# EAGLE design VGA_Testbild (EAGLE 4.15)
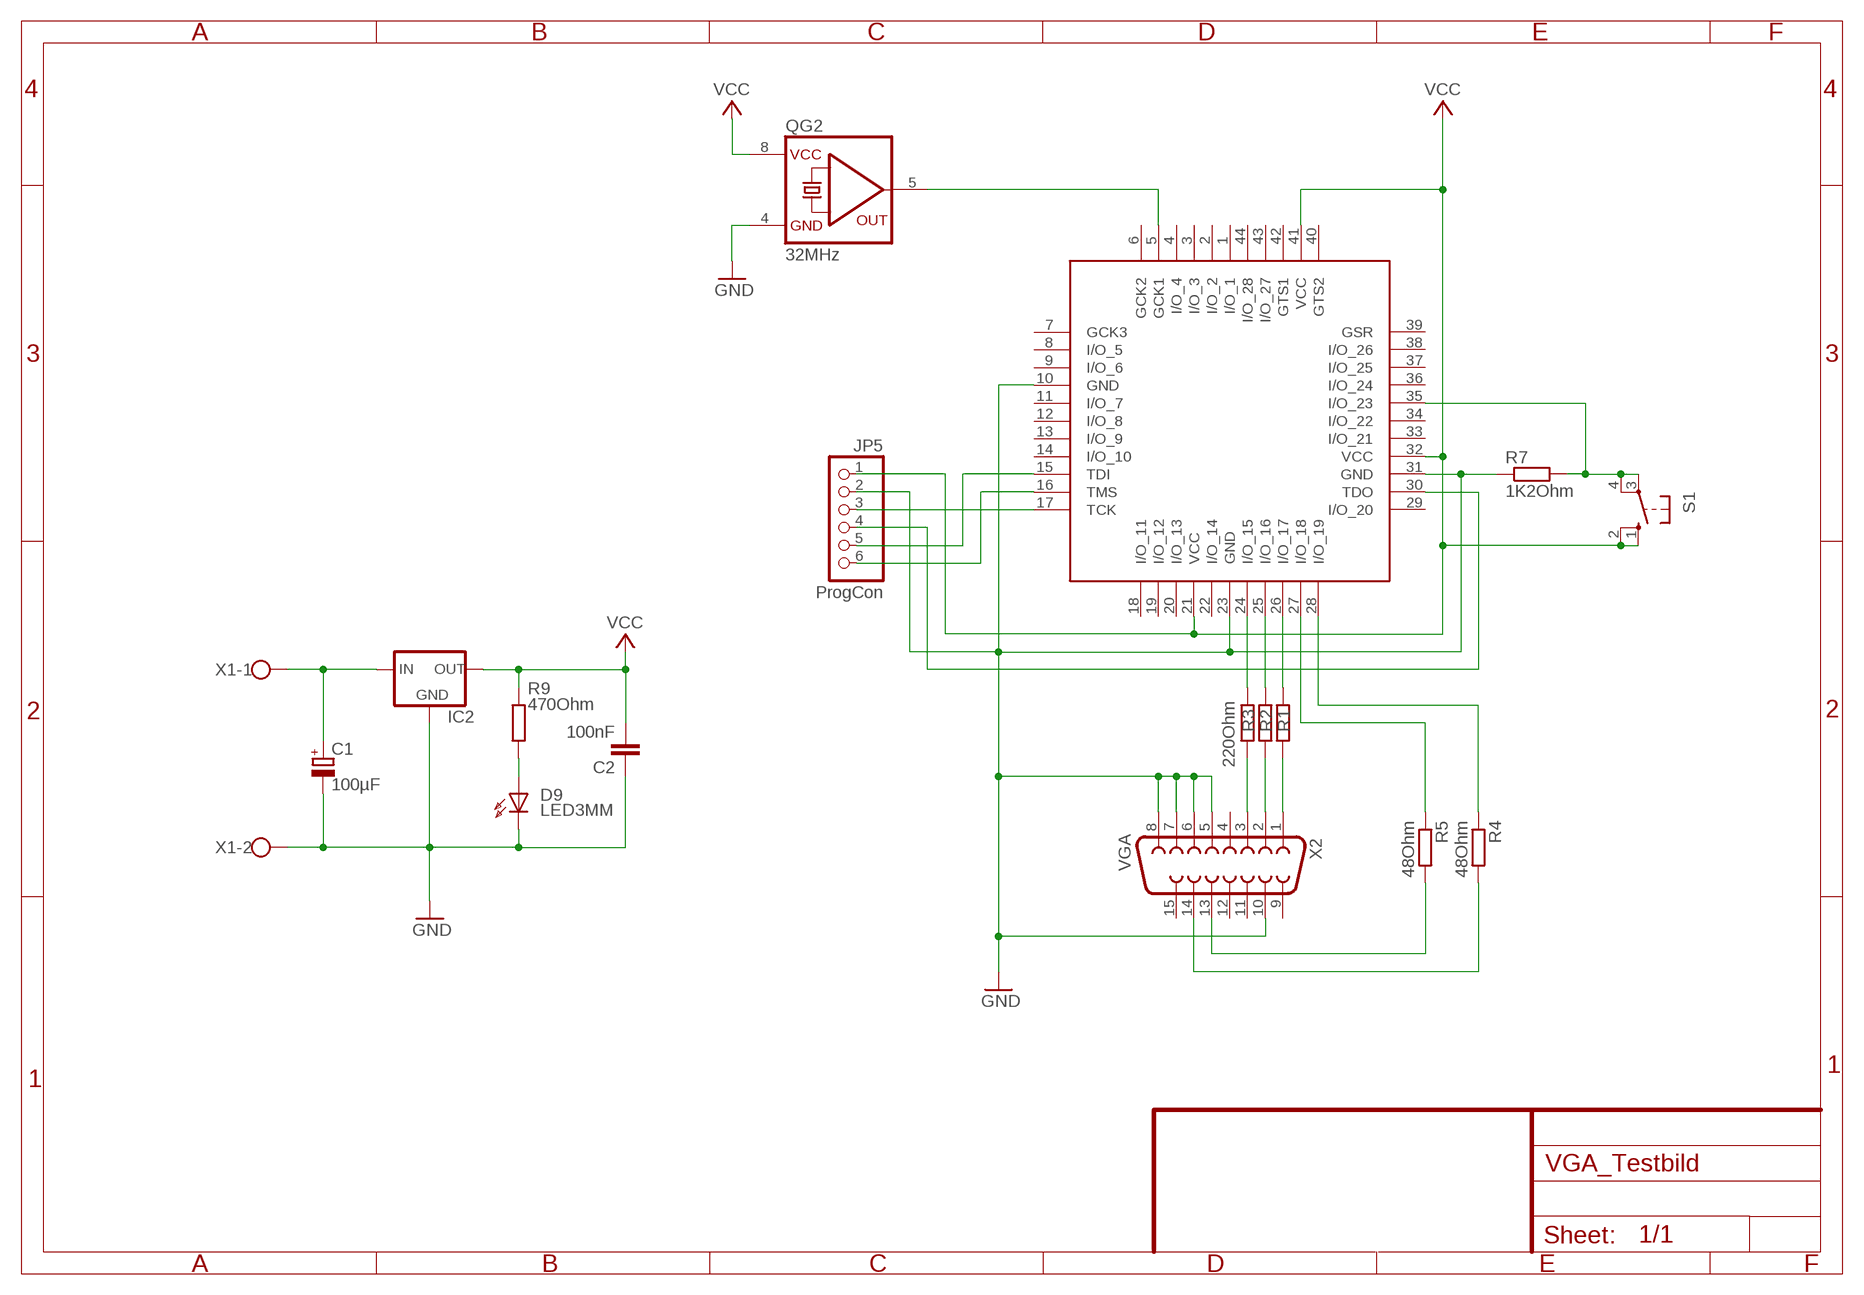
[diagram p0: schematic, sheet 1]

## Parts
C1  100µF  CPOL-EUE2.5-6  [E2,5-6]
C2  100nF  C-EU050-025X075  [C050-025X075]
D9  LED3MM  [LED3MM]
IC1  XC9536PLCC44S  [S44]
IC2  78XXL  [78XXL]
JP5  ProgCon  PINHD-1X6  [1X06]
QG2  32MHz  QG5460  [DIL08S]
R1  R-EU_0207/10  [0207/10]
R2  R-EU_0207/10  [0207/10]
R3  220Ohm  R-EU_0207/10  [0207/10]
R4  48Ohm  R-EU_0207/10  [0207/10]
R5  48Ohm  R-EU_0207/10  [0207/10]
R7  1K2Ohm  R-EU_0207/10  [0207/10]
R9  470Ohm  R-EU_0207/10  [0207/10]
S1  10-XX  [B3F-10XX]
X1  W237-02P  [W237-132]
X2  VGA  F15HDH  [HDF15H]

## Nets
GND: C1.- C2.1 D9.K(C) IC1.10(GND) IC1.23(GND) IC1.31(GND) IC2.GND JP5.2 QG2.4(GND) R7.1 X1.2 X2.5 X2.6 X2.7 X2.8 X2.10
N$1: R3.1 X2.3
N$2: R2.1 X2.2
N$3: R1.1 X2.1
N$4: IC1.24(I/O_15) R3.2
N$5: IC1.25(I/O_16) R2.2
N$6: IC1.26(I/O_17) R1.2
N$7: R5.2 X2.13
N$8: R4.2 X2.14
N$9: IC1.27(I/O_18) R5.1
N$10: IC1.15(TDI) JP5.5
N$11: IC1.16(TMS) JP5.6
N$12: IC1.17(TCK) JP5.3
N$13: IC1.28(I/O_19) R4.1
N$14: IC1.5(GCK1) QG2.5(OUT)
N$15: IC1.35(I/O_23) R7.2 S1.3(P) S1.4(P1)
N$22: IC1.30(TDO) JP5.4
N$47: C1.+ IC2.IN X1.1
N$48: D9.A R9.1
VCC: C2.2 IC1.21(VCC) IC1.32(VCC) IC1.41(VCC) IC2.OUT JP5.1 QG2.8(VCC) R9.2 S1.1(S) S1.2(S1)
Unconnected: IC1.1(I/O_1) IC1.2(I/O_2) IC1.3(I/O_3) IC1.4(I/O_4) IC1.6(GCK2) IC1.7(GCK3) IC1.8(I/O_5) IC1.9(I/O_6) IC1.11(I/O_7) IC1.12(I/O_8) IC1.13(I/O_9) IC1.14(I/O_10) IC1.18(I/O_11) IC1.19(I/O_12) IC1.20(I/O_13) IC1.22(I/O_14) IC1.29(I/O_20) IC1.33(I/O_21) IC1.34(I/O_22) IC1.36(I/O_24) IC1.37(I/O_25) IC1.38(I/O_26) IC1.39(GSR) IC1.40(GTS2) IC1.42(GTS1) IC1.43(I/O_27) IC1.44(I/O_28) X2.4 X2.9 X2.11 X2.12 X2.15

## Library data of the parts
C1 = rcl:CPOL-EU: POLARIZED CAPACITOR, European symbol
C2 = rcl:C-EU: CAPACITOR, European symbol
D9 = led:LED3MM: LED
IC1 = xilinx:XC9536: Xilinx CPLD Cells 36 Gates 800
IC2 = v-reg:78XXL: VOLTAGE REGULATOR
JP5 = pinhead:PINHD-1X6: PIN HEADER
QG2 = crystal:QG5460: CRYSTAL RESONATOR
R1-R5 R7 R9 = rcl:R-EU_: RESISTOR, European symbol
S1 = switch-omron:10-XX: OMRON SWITCH
X1 = con-wago-508:W237-02P: WAGO SREW CLAMP
X2 = con-subd:F15: SUB-D

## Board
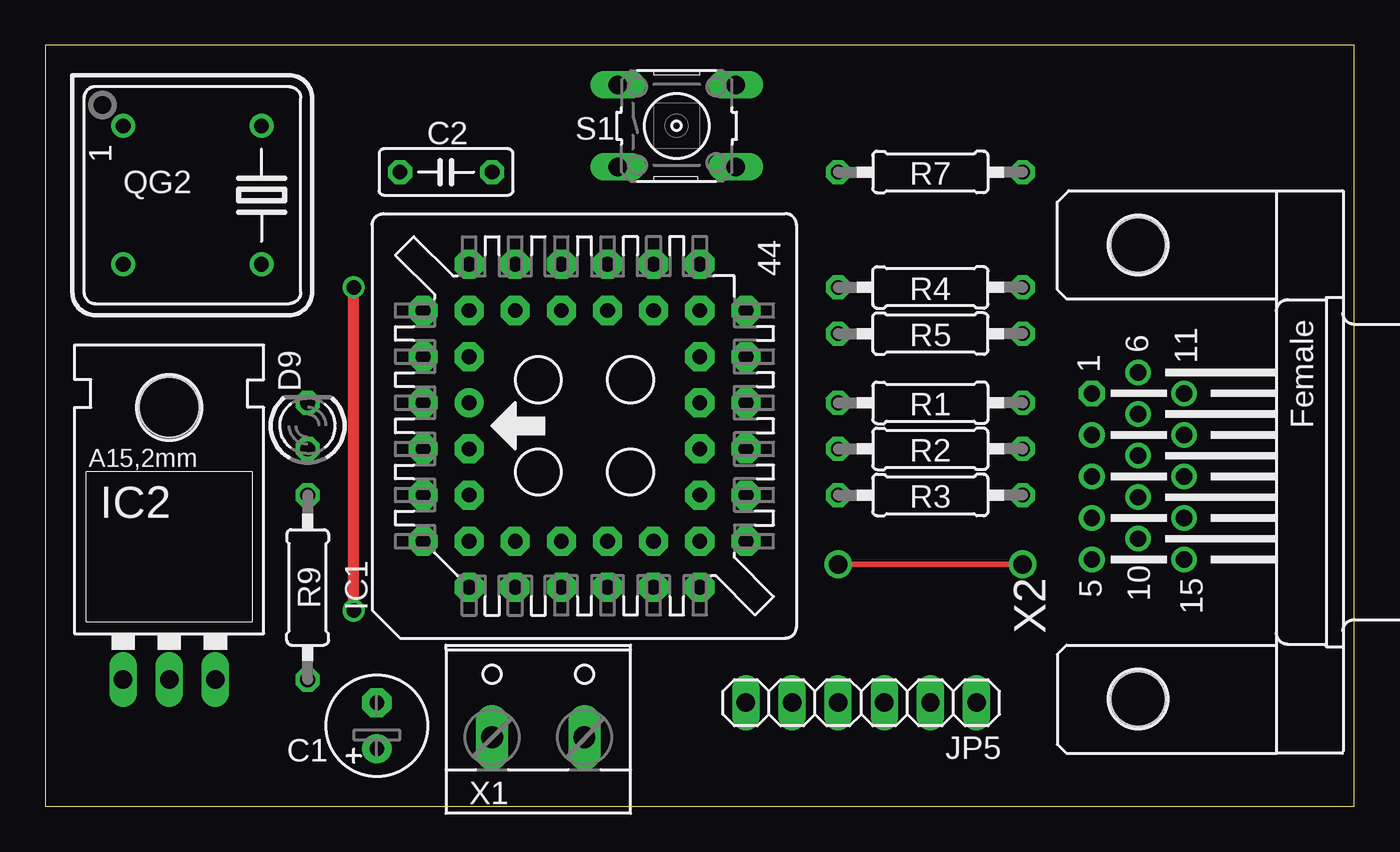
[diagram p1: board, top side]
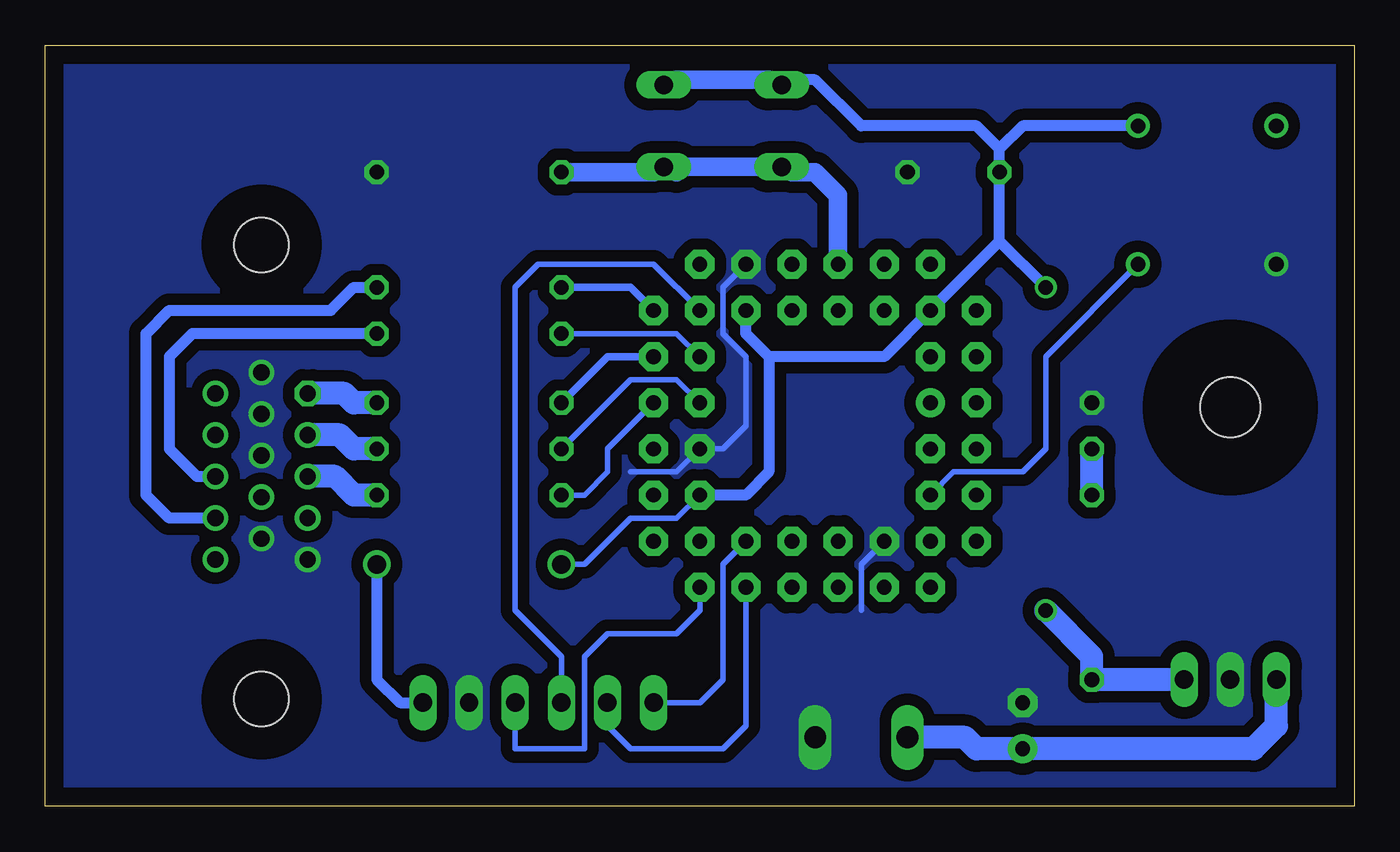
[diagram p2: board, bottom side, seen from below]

Size 72.06 x 41.89 mm. Coordinates in mm from the lower left corner, seen from the top.
Outline: 72.06,0 72.06,41.89 0,41.89 0,0 72.06,0
Copper layers (1*16): Top 0.035mm / dielectric 1.5mm / Bottom 0.035mm
Design rules "default": minimum track width 10mil, minimum drill 24mil, track to track 8mil, track to pad 8mil, pad to pad 8mil, via to via 8mil, smd to smd 8mil, copper to edge 40mil, drill to drill 8mil, minimum pad ring 10mil, minimum via ring 8mil, stop-mask expansion 4mil, vias tented up to drill 0mil, thermal gap 10mil

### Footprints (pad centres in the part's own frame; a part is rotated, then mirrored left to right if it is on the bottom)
E2,5-6 = drill 0.813 pad 1.6 round: + -1.27,0 | drill 0.813 pad 1.6 octagon: - 1.27,0
C050-025X075 = drill 0.813 octagon: 1 -2.54,0; 2 2.54,0
LED3MM = drill 0.813 octagon: A -1.27,0; K 1.27,0
S44 = drill 0.813 pad 1.6 round: 1 1.27,5.08 | drill 0.813 pad 1.6 octagon: 2 -1.27,7.62; 3 -1.27,5.08; 4 -3.81,7.62; 5 -3.81,5.08; 6 -6.35,7.62; 7 -8.89,5.08; 8 -6.35,5.08; 9 -8.89,2.54; 10 -6.35,2.54; 11 -8.89,0; 12 -6.35,0; 13 -8.89,-2.54; 14 -6.35,-2.54; 15 -8.89,-5.08; 16 -6.35,-5.08; 17 -8.89,-7.62; 18 -6.35,-10.16; 19 -6.35,-7.62; 20 -3.81,-10.16; 21 -3.81,-7.62; 22 -1.27,-10.16; 23 -1.27,-7.62; 24 1.27,-10.16; 25 1.27,-7.62; 26 3.81,-10.16; 27 3.81,-7.62; 28 6.35,-10.16; 29 8.89,-7.62; 30 6.35,-7.62; 31 8.89,-5.08; 32 6.35,-5.08; 33 8.89,-2.54; 34 6.35,-2.54; 35 8.89,0; 36 6.35,0; 37 8.89,2.54; 38 6.35,2.54; 39 8.89,5.08; 40 6.35,7.62; 41 6.35,5.08; 42 3.81,7.62; 43 3.81,5.08; 44 1.27,7.62
78XXL = drill 1.016 long: GND 0,-3.81; IN -2.54,-3.81; OUT 2.54,-3.81 | hole 3.302: 0,11.176
1X06 = drill 1.016 long: 1 -6.35,0; 2 -3.81,0; 3 -1.27,0; 4 1.27,0; 5 3.81,0; 6 6.35,0
DIL08S = drill 0.813 round: 1 -3.81,-3.81; 4 3.81,-3.81; 5 3.81,3.81; 8 -3.81,3.81
0207/10 = drill 0.813 octagon: 1 -5.08,0; 2 5.08,0
B3F-10XX = drill 1.016 long: 1 -3.251,2.261; 2 3.251,2.261; 3 -3.251,-2.261; 4 3.251,-2.261
W237-132 = drill 1.194 long: 1 -2.54,-0.635; 2 2.54,-0.635
HDF15H = drill 0.9 octagon: 1 4.329,2.54 | drill 0.9 round: 2 2.043,2.54; 3 -0.243,2.54; 4 -2.529,2.54; 5 -4.815,2.54; 6 5.472,0; 7 3.186,0; 8 0.9,0; 9 -1.386,0; 10 -3.672,0; 11 4.329,-2.54; 12 2.043,-2.54; 13 -0.243,-2.54; 14 -2.529,-2.54; 15 -4.815,-2.54 | hole 3: -12.5,0; 12.5,0

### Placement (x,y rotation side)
C1  18.25,4.44 90 top
C2  22.06,34.92 180 top
D9  14.44,20.95 90 top
IC1  28.41,20.95 90 top
IC2  6.82,10.79 0 top
JP5  44.92,5.71 180 top
QG2  8.09,33.65 270 top
R1  48.73,22.22 180 top
R2  48.73,19.68 180 top
R3  48.73,17.14 180 top
R4  48.73,28.57 0 top
R5  48.73,26.03 0 top
R7  48.73,34.92 180 top
R9  14.44,12.06 270 top
S1  34.76,37.46 0 top
X1  27.14,4.44 0 top
X2  60.16,18.41 90 top

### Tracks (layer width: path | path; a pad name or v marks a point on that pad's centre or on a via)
GND
  Bottom 0.305: IC1.10 27.14,13.33 27.14,10.79 | IC1.31 34.76,28.57 34.76,26.03 33.49,24.76 33.49,20.95 34.76,19.68 IC1.23 37.3,18.41 39.84,18.41
  pour Bottom (isolate 0.635, no thermals): 0.47,0.63 0.47,41.27 71.59,41.27 71.59,0.63
N$1
  Bottom 1.27: R3.1 55.08,17.14 56.11,18.17 X2.3
N$2
  Bottom 1.27: R2.1 55.08,19.68 55.85,20.45 X2.2
N$3
  Bottom 1.27: R1.1 55.08,22.22 55.6,22.74 X2.1
N$4
  Bottom 0.305: IC1.24 41.11,19.68 41.11,18.41 42.38,17.14 R3.2
N$5
  Bottom 0.305: IC1.25 37.3,23.49 39.84,23.49 R2.2
N$6
  Bottom 0.406: IC1.26 41.11,24.76 R1.2
N$7
  Bottom 0.61: X2.13 63.73,18.17 65.24,19.68 65.24,24.76 63.97,26.03 R5.2
N$8
  Bottom 0.61: R4.2 55.08,28.57 56.35,27.3 65.24,27.3 66.51,26.03 66.51,17.14 65.24,15.87 X2.14
N$9
  Bottom 0.305: IC1.27 37.3,26.03 R5.1
N$10
  Bottom 0.305: IC1.15 33.49,4.44 34.76,3.17 39.84,3.17 41.11,4.44 JP5.5
N$11
  Bottom 0.305: IC1.16 34.76,13.33 34.76,6.98 36.03,5.71 JP5.6
N$12
  Bottom 0.305: IC1.17 36.03,10.79 37.3,9.52 41.11,9.52 42.38,8.25 42.38,3.17 46.19,3.17 JP5.3
N$13
  Bottom 0.406: IC1.28 39.84,28.57 R4.1
N$14
  Bottom 0.305: IC1.5 22.06,18.41 18.25,18.41 16.98,19.68 16.98,24.76 QG2.5
N$15
  Bottom 0.406: 31.23,35.2 S1.3 | 37.02,35.2 37.3,34.92 | S1.4 38.29,35.2
  Bottom 1.016: IC1.35 28.41,33.65 29.68,34.92 30.95,34.92 31.23,35.2 | S1.3 37.02,35.2 | S1.4 37.58,35.2 37.3,34.92 | 38.29,35.2 38.57,34.92 R7.2
N$22
  Bottom 0.305: IC1.30 38.57,29.84 44.92,29.84 46.19,28.57 46.19,10.79 43.65,8.25 JP5.4
N$47
  Bottom 1.27: X1.1 21.43,3.81 20.79,3.17 C1.+ 5.55,3.17 4.28,4.44 IC2.IN
N$48
  Bottom 1.27: R9.1 D9.A
VCC  (via drill 0.81, 1.02)
  Top 0.305: v43.65,13.33 v53.81,13.33
  Top 0.61: v16.98,10.79 v16.98,28.57
  Bottom 0.305: IC1.21 37.3,15.87 39.84,15.87 42.38,13.33 v43.65,13.33
  Bottom 0.61: 32.22,24.76 25.87,24.76 IC1.41 19.52,31.11 | IC1.32 33.49,26.03 32.22,24.76 | 32.22,24.76 32.22,18.41 33.49,17.14 IC1.21 | v53.81,13.33 53.81,6.98 52.54,5.71 JP5.1 | QG2.8 18.25,37.46 19.52,36.19 | 19.52,36.19 C2.2 19.52,31.11 | v16.98,28.57 19.52,31.11 | 32.22,40 29.68,40 27.14,37.46 20.79,37.46 19.52,36.19
  Bottom 1.016: S1.2 37.58,39.72 37.3,40 32.22,40 31.94,39.72 S1.1
  Bottom 1.27: IC2.OUT R9.2 14.44,8.25 v16.98,10.79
